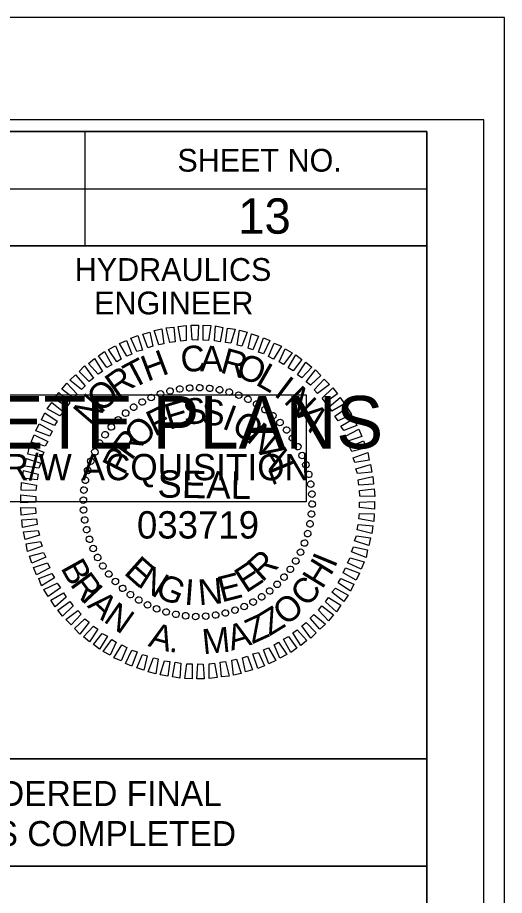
# Model space of a CAD drawing. Extents: x 1779926 to 1781610, y 620464 to 621564.
# Drawn here: x 1781503.2 to 1781610, y 621371.7 to 621564.2 of the extents above; entities that cross this region are included whole.
import ezdxf

# ---------------------------------------------------------------- set-up
doc = ezdxf.new("R2010")
doc.units = 0
for name, color, linetype in [('Old_Level_58', 7, 'Continuous'), ('Sheet Cutting Line CELL', 7, 'Continuous'), ('Sheet Data Field CELL', 7, 'Continuous'), ('Sheet Plot Border Inside CELL', 7, 'Continuous'), ('Sheet Plot Border Outside CELL', 7, 'Continuous'), ('Sheet Professional Seal CELL', 7, 'Continuous'), ('Sheet Profile CELL', 7, 'Continuous'), ('Sheet Profile Grid Major CELL', 7, 'Continuous'), ('Sheet Profile Grid Minor CELL', 7, 'Continuous'), ('Sheet Sticker Exception Certification CELL', 7, 'Continuous'), ('Sheet Sticker Incomplete CELL', 7, 'Continuous')]:
    doc.layers.add(name, color=color, linetype=linetype)

msp = doc.modelspace()

# ---------------------------------------------------------------- linework, layer by layer
at = {"layer": 'Old_Level_58'}
msp.add_lwpolyline([(1781392.9, 621378.13), (1781592.95, 621378.13), (1781592.95, 621314.19), (1781392.9, 621314.19)], close=True, dxfattribs=at)
at = {"layer": 'Sheet Cutting Line CELL'}
msp.add_line((1781609.96, 621564.19), (1779925.96, 621564.19), dxfattribs=at)
at = {"layer": 'Sheet Plot Border Inside CELL'}
msp.add_lwpolyline([(1779938.96, 620486.64), (1781605.46, 620486.64), (1781605.46, 621541.74), (1779938.96, 621541.74)], close=True, dxfattribs=at)
at = {"layer": 'Sheet Plot Border Outside CELL'}
msp.add_lwpolyline([(1779925.96, 620464.19), (1781609.96, 620464.19), (1781609.96, 621564.19), (1779925.96, 621564.19)], close=True, dxfattribs=at)
at = {"layer": 'Sheet Professional Seal CELL'}
for p, q in [((1781538.82, 621482.71), (1781538.82, 621482.71)), ((1781540.97, 621483.01), (1781540.97, 621483.01)), ((1781543.17, 621483.06), (1781543.17, 621483.06)), ((1781545.37, 621482.91), (1781545.37, 621482.91)), ((1781547.52, 621482.56), (1781547.52, 621482.56)), ((1781532.52, 621480.91), (1781532.52, 621480.91)), ((1781534.52, 621481.71), (1781534.52, 621481.71)), ((1781536.62, 621482.31), (1781536.62, 621482.31)), ((1781549.62, 621482.11), (1781549.62, 621482.11)), ((1781551.72, 621481.41), (1781551.72, 621481.41)), ((1781553.72, 621480.51), (1781553.72, 621480.51)), ((1781528.67, 621478.76), (1781528.67, 621478.76)), ((1781530.57, 621479.91), (1781530.57, 621479.91)), ((1781555.67, 621479.51), (1781555.67, 621479.51)), ((1781526.92, 621477.51), (1781526.92, 621477.51)), ((1781557.47, 621478.26), (1781557.47, 621478.26)), ((1781559.22, 621476.91), (1781559.22, 621476.91)), ((1781525.27, 621476.01), (1781525.27, 621476.01)), ((1781560.77, 621475.41), (1781560.77, 621475.41)), ((1781523.77, 621474.46), (1781523.77, 621474.46)), ((1781562.27, 621473.76), (1781562.27, 621473.76)), ((1781521.17, 621470.91), (1781521.17, 621470.91)), ((1781522.42, 621472.71), (1781522.42, 621472.71)), ((1781563.52, 621472.01), (1781563.52, 621472.01)), ((1781520.17, 621468.96), (1781520.17, 621468.96)), ((1781564.67, 621470.11), (1781564.67, 621470.11)), ((1781565.67, 621468.16), (1781565.67, 621468.16)), ((1781519.27, 621466.96), (1781519.27, 621466.96)), ((1781566.47, 621466.16), (1781566.47, 621466.16)), ((1781518.57, 621464.86), (1781518.57, 621464.86)), ((1781567.07, 621464.06), (1781567.07, 621464.06)), ((1781518.12, 621462.76), (1781518.12, 621462.76)), ((1781567.47, 621461.86), (1781567.47, 621461.86)), ((1781517.77, 621460.61), (1781517.77, 621460.61)), ((1781567.77, 621459.71), (1781567.77, 621459.71)), ((1781517.62, 621458.41), (1781517.62, 621458.41)), ((1781542.72, 621457.96), (1781542.72, 621457.96)), ((1781567.82, 621457.51), (1781567.82, 621457.51)), ((1781517.67, 621456.21), (1781517.67, 621456.21)), ((1781517.97, 621454.06), (1781517.97, 621454.06)), ((1781567.67, 621455.31), (1781567.67, 621455.31)), ((1781518.37, 621451.86), (1781518.37, 621451.86)), ((1781567.32, 621453.16), (1781567.32, 621453.16)), ((1781518.97, 621449.76), (1781518.97, 621449.76)), ((1781566.87, 621451.06), (1781566.87, 621451.06)), ((1781519.77, 621447.76), (1781519.77, 621447.76)), ((1781566.17, 621448.96), (1781566.17, 621448.96)), ((1781565.27, 621446.96), (1781565.27, 621446.96)), ((1781520.77, 621445.81), (1781520.77, 621445.81)), ((1781521.92, 621443.91), (1781521.92, 621443.91)), ((1781564.27, 621445.01), (1781564.27, 621445.01)), ((1781523.17, 621442.16), (1781523.17, 621442.16)), ((1781563.02, 621443.21), (1781563.02, 621443.21)), ((1781524.67, 621440.51), (1781524.67, 621440.51)), ((1781561.67, 621441.46), (1781561.67, 621441.46)), ((1781526.22, 621439.01), (1781526.22, 621439.01)), ((1781558.52, 621438.41), (1781558.52, 621438.41)), ((1781560.17, 621439.91), (1781560.17, 621439.91)), ((1781527.97, 621437.66), (1781527.97, 621437.66)), ((1781529.77, 621436.41), (1781529.77, 621436.41)), ((1781556.77, 621437.16), (1781556.77, 621437.16)), ((1781531.72, 621435.41), (1781531.72, 621435.41)), ((1781533.72, 621434.51), (1781533.72, 621434.51)), ((1781552.92, 621435.01), (1781552.92, 621435.01)), ((1781554.87, 621436.01), (1781554.87, 621436.01)), ((1781535.82, 621433.81), (1781535.82, 621433.81)), ((1781537.92, 621433.36), (1781537.92, 621433.36)), ((1781540.07, 621433.01), (1781540.07, 621433.01)), ((1781542.27, 621432.86), (1781542.27, 621432.86)), ((1781544.47, 621432.91), (1781544.47, 621432.91)), ((1781546.62, 621433.21), (1781546.62, 621433.21)), ((1781548.82, 621433.61), (1781548.82, 621433.61)), ((1781550.92, 621434.21), (1781550.92, 621434.21))]:
    msp.add_line(p, q, dxfattribs=at)
for points in [[(1781534.22, 621492.41), (1781533.17, 621495.56), (1781534.87, 621495.91), (1781535.27, 621492.66)], [(1781536.62, 621492.96), (1781535.82, 621496.16), (1781537.47, 621496.31), (1781537.82, 621493.11)], [(1781539.02, 621493.26), (1781538.47, 621496.46), (1781540.17, 621496.66), (1781540.22, 621493.41)], [(1781541.52, 621493.51), (1781541.27, 621496.76), (1781542.92, 621496.71), (1781542.72, 621493.46)], [(1781543.92, 621493.46), (1781543.92, 621496.71), (1781545.57, 621496.66), (1781545.12, 621493.41)], [(1781546.42, 621493.31), (1781546.62, 621496.56), (1781548.27, 621496.26), (1781547.62, 621493.11)], [(1781548.82, 621492.91), (1781549.27, 621496.11), (1781550.92, 621495.86), (1781550.02, 621492.76)], [(1781529.37, 621490.96), (1781528.07, 621493.86), (1781529.57, 621494.46), (1781530.62, 621491.26)], [(1781531.82, 621491.76), (1781530.67, 621494.76), (1781532.22, 621495.21), (1781532.87, 621492.11)], [(1781551.37, 621492.36), (1781551.87, 621495.61), (1781553.57, 621495.21), (1781552.42, 621492.11)], [(1781553.77, 621491.71), (1781554.52, 621494.81), (1781556.07, 621494.31), (1781554.82, 621491.36)], [(1781556.02, 621490.81), (1781557.17, 621493.96), (1781558.57, 621493.36), (1781557.17, 621490.46)], [(1781525.02, 621488.71), (1781523.17, 621491.41), (1781524.72, 621492.21), (1781525.97, 621489.31)], [(1781527.17, 621489.91), (1781525.57, 621492.71), (1781527.12, 621493.41), (1781528.27, 621490.36)], [(1781558.27, 621489.86), (1781559.52, 621492.81), (1781561.07, 621492.11), (1781559.37, 621489.31)], [(1781522.82, 621487.46), (1781520.97, 621490.01), (1781522.27, 621490.96), (1781523.92, 621488.06)], [(1781560.57, 621488.71), (1781561.92, 621491.56), (1781563.42, 621490.71), (1781561.52, 621488.11)], [(1781562.52, 621487.36), (1781564.27, 621490.26), (1781565.57, 621489.21), (1781563.62, 621486.76)], [(1781520.92, 621485.96), (1781518.77, 621488.36), (1781520.12, 621489.41), (1781521.87, 621486.61)], [(1781564.57, 621485.86), (1781566.42, 621488.61), (1781567.72, 621487.51), (1781565.52, 621485.16)], [(1781518.92, 621484.41), (1781516.72, 621486.61), (1781517.92, 621487.81), (1781519.87, 621485.11)], [(1781566.47, 621484.31), (1781568.52, 621486.91), (1781569.72, 621485.71), (1781567.42, 621483.56)], [(1781517.27, 621482.66), (1781514.72, 621484.71), (1781515.97, 621485.86), (1781518.07, 621483.46)], [(1781568.27, 621482.56), (1781570.42, 621484.91), (1781571.62, 621483.71), (1781569.02, 621481.76)], [(1781515.52, 621480.76), (1781512.92, 621482.71), (1781514.02, 621484.01), (1781516.22, 621481.66)], [(1781570.02, 621480.76), (1781572.32, 621483.01), (1781573.37, 621481.66), (1781570.72, 621479.76)], [(1781514.02, 621478.86), (1781511.32, 621480.56), (1781512.27, 621482.01), (1781514.67, 621479.81)], [(1781571.52, 621478.81), (1781573.97, 621480.91), (1781574.92, 621479.46), (1781572.12, 621477.86)], [(1781512.52, 621476.86), (1781509.72, 621478.36), (1781510.72, 621479.76), (1781513.32, 621477.76)], [(1781572.82, 621476.76), (1781575.47, 621478.66), (1781576.42, 621477.16), (1781573.52, 621475.76)], [(1781511.32, 621474.71), (1781508.47, 621475.96), (1781509.22, 621477.51), (1781511.92, 621475.66)], [(1781510.32, 621472.41), (1781507.22, 621473.56), (1781507.97, 621475.11), (1781510.82, 621473.51)], [(1781574.12, 621474.56), (1781576.92, 621476.31), (1781577.57, 621474.76), (1781574.72, 621473.61)], [(1781575.12, 621472.41), (1781578.07, 621473.91), (1781578.72, 621472.31), (1781575.62, 621471.31)], [(1781509.32, 621470.21), (1781506.22, 621471.11), (1781506.87, 621472.66), (1781509.87, 621471.26)], [(1781576.02, 621470.06), (1781579.07, 621471.36), (1781579.62, 621469.81), (1781576.52, 621469.01)], [(1781508.57, 621467.81), (1781505.47, 621468.46), (1781505.82, 621470.11), (1781508.97, 621468.86)], [(1781507.92, 621465.41), (1781504.82, 621465.81), (1781505.17, 621467.51), (1781508.32, 621466.46)], [(1781576.82, 621467.66), (1781580.02, 621468.81), (1781580.32, 621467.16), (1781577.17, 621466.61)], [(1781577.42, 621465.26), (1781580.57, 621466.21), (1781580.87, 621464.51), (1781577.72, 621464.21)], [(1781507.52, 621462.86), (1781504.32, 621463.16), (1781504.52, 621464.86), (1781507.77, 621464.06)], [(1781577.87, 621462.86), (1781581.12, 621463.56), (1781581.27, 621461.86), (1781578.07, 621461.66)], [(1781507.27, 621460.46), (1781504.02, 621460.56), (1781504.12, 621462.21), (1781507.37, 621461.66)], [(1781507.22, 621457.96), (1781503.97, 621457.81), (1781503.97, 621459.51), (1781507.22, 621459.16)], [(1781578.17, 621460.46), (1781581.42, 621460.86), (1781581.52, 621459.16), (1781578.27, 621459.26)], [(1781578.22, 621457.96), (1781581.47, 621458.11), (1781581.47, 621456.41), (1781578.22, 621456.76)], [(1781507.27, 621455.46), (1781504.02, 621455.06), (1781503.92, 621456.76), (1781507.17, 621456.66)], [(1781578.17, 621455.46), (1781581.42, 621455.36), (1781581.32, 621453.71), (1781578.07, 621454.26)], [(1781507.57, 621453.06), (1781504.32, 621452.36), (1781504.17, 621454.06), (1781507.37, 621454.26)], [(1781508.02, 621450.66), (1781504.87, 621449.71), (1781504.57, 621451.41), (1781507.72, 621451.71)], [(1781577.92, 621453.06), (1781581.12, 621452.76), (1781580.92, 621451.06), (1781577.67, 621451.86)], [(1781577.52, 621450.51), (1781580.62, 621450.11), (1781580.27, 621448.41), (1781577.12, 621449.46)], [(1781508.62, 621448.26), (1781505.42, 621447.11), (1781505.12, 621448.76), (1781508.27, 621449.31)], [(1781576.87, 621448.11), (1781579.97, 621447.46), (1781579.62, 621445.81), (1781576.47, 621447.06)], [(1781509.42, 621445.86), (1781506.37, 621444.56), (1781505.82, 621446.11), (1781508.92, 621446.91)], [(1781510.32, 621443.51), (1781507.37, 621442.01), (1781506.72, 621443.61), (1781509.82, 621444.61)], [(1781576.12, 621445.71), (1781579.22, 621444.81), (1781578.57, 621443.26), (1781575.57, 621444.66)], [(1781511.32, 621441.36), (1781508.52, 621439.61), (1781507.87, 621441.16), (1781510.72, 621442.31)], [(1781575.12, 621443.51), (1781578.22, 621442.36), (1781577.47, 621440.81), (1781574.62, 621442.41)], [(1781512.62, 621439.16), (1781509.97, 621437.26), (1781509.02, 621438.76), (1781511.92, 621440.16)], [(1781574.12, 621441.21), (1781576.97, 621439.96), (1781576.22, 621438.41), (1781573.52, 621440.26)], [(1781572.92, 621439.06), (1781575.72, 621437.56), (1781574.72, 621436.16), (1781572.12, 621438.16)], [(1781513.92, 621437.11), (1781511.47, 621435.01), (1781510.52, 621436.46), (1781513.32, 621438.06)], [(1781571.42, 621437.06), (1781574.12, 621435.36), (1781573.17, 621433.91), (1781570.77, 621436.11)], [(1781515.42, 621435.16), (1781513.12, 621432.91), (1781512.07, 621434.26), (1781514.72, 621436.16)], [(1781569.92, 621435.16), (1781572.52, 621433.21), (1781571.42, 621431.91), (1781569.22, 621434.26)], [(1781517.17, 621433.36), (1781515.02, 621431.01), (1781513.82, 621432.21), (1781516.42, 621434.16)], [(1781518.97, 621431.61), (1781516.92, 621429.01), (1781515.72, 621430.21), (1781518.02, 621432.36)], [(1781568.17, 621433.26), (1781570.72, 621431.21), (1781569.47, 621430.06), (1781567.37, 621432.46)], [(1781520.87, 621430.06), (1781519.02, 621427.31), (1781517.72, 621428.41), (1781519.92, 621430.76)], [(1781566.52, 621431.51), (1781568.72, 621429.31), (1781567.52, 621428.11), (1781565.57, 621430.81)], [(1781522.92, 621428.56), (1781521.17, 621425.66), (1781519.87, 621426.71), (1781521.82, 621429.16)], [(1781564.52, 621429.96), (1781566.67, 621427.56), (1781565.32, 621426.51), (1781563.57, 621429.31)], [(1781524.87, 621427.21), (1781523.52, 621424.36), (1781522.02, 621425.21), (1781523.92, 621427.81)], [(1781527.17, 621426.06), (1781525.92, 621423.11), (1781524.37, 621423.81), (1781526.07, 621426.61)], [(1781560.42, 621427.21), (1781562.27, 621424.51), (1781560.72, 621423.71), (1781559.47, 621426.61)], [(1781562.62, 621428.46), (1781564.47, 621425.91), (1781563.17, 621424.96), (1781561.52, 621427.86)], [(1781529.42, 621425.11), (1781528.27, 621421.96), (1781526.87, 621422.56), (1781528.27, 621425.46)], [(1781556.07, 621424.96), (1781557.37, 621422.06), (1781555.87, 621421.46), (1781554.82, 621424.66)], [(1781558.27, 621426.01), (1781559.87, 621423.21), (1781558.32, 621422.51), (1781557.17, 621425.56)], [(1781531.67, 621424.21), (1781530.92, 621421.11), (1781529.37, 621421.61), (1781530.62, 621424.56)], [(1781534.07, 621423.56), (1781533.57, 621420.31), (1781531.87, 621420.71), (1781533.02, 621423.81)], [(1781536.62, 621423.01), (1781536.17, 621419.81), (1781534.52, 621420.06), (1781535.42, 621423.16)], [(1781539.02, 621422.61), (1781538.82, 621419.36), (1781537.17, 621419.66), (1781537.82, 621422.81)], [(1781548.82, 621422.96), (1781549.62, 621419.76), (1781547.97, 621419.61), (1781547.62, 621422.81)], [(1781551.22, 621423.51), (1781552.27, 621420.36), (1781550.57, 621420.01), (1781550.17, 621423.26)], [(1781553.62, 621424.16), (1781554.77, 621421.16), (1781553.22, 621420.71), (1781552.57, 621423.81)], [(1781541.52, 621422.46), (1781541.52, 621419.21), (1781539.87, 621419.26), (1781540.32, 621422.51)], [(1781543.92, 621422.41), (1781544.17, 621419.16), (1781542.52, 621419.21), (1781542.72, 621422.46)], [(1781546.42, 621422.66), (1781546.97, 621419.46), (1781545.27, 621419.26), (1781545.22, 621422.51)]]:
    msp.add_lwpolyline(points, close=True, dxfattribs=at)
for centre, major_axis in [((1781534.56, 621481.67), (-0.234, 0.681)), ((1781536.65, 621482.29), (-0.174, 0.699)), ((1781538.8, 621482.73), (-0.113, 0.711)), ((1781540.97, 621482.97), (-0.05, 0.718)), ((1781543.16, 621483.03), (0.013, 0.72)), ((1781545.34, 621482.9), (0.075, 0.716)), ((1781547.51, 621482.57), (0.137, 0.707)), ((1781549.64, 621482.06), (0.198, 0.692)), ((1781530.56, 621479.89), (-0.349, 0.63)), ((1781532.52, 621480.87), (-0.293, 0.658)), ((1781551.71, 621481.37), (0.258, 0.672)), ((1781553.72, 621480.5), (0.316, 0.647)), ((1781528.7, 621478.75), (-0.403, 0.597)), ((1781555.64, 621479.45), (0.371, 0.617)), ((1781557.46, 621478.25), (0.423, 0.582)), ((1781525.3, 621476), (-0.5, 0.518)), ((1781526.94, 621477.45), (-0.453, 0.56)), ((1781559.18, 621476.88), (0.472, 0.543)), ((1781523.79, 621474.41), (-0.543, 0.472)), ((1781560.76, 621475.38), (0.518, 0.5)), ((1781522.43, 621472.7), (-0.582, 0.423)), ((1781562.21, 621473.74), (0.56, 0.453)), ((1781563.51, 621471.98), (0.597, 0.403)), ((1781521.22, 621470.87), (-0.617, 0.371)), ((1781564.66, 621470.11), (0.63, 0.349)), ((1781520.18, 621468.95), (-0.647, 0.316)), ((1781565.63, 621468.16), (0.658, 0.293)), ((1781519.31, 621466.94), (-0.672, 0.258)), ((1781518.61, 621464.87), (-0.692, 0.198)), ((1781566.44, 621466.12), (0.681, 0.234)), ((1781518.1, 621462.74), (-0.707, 0.137)), ((1781567.06, 621464.02), (0.699, 0.174)), ((1781517.78, 621460.58), (-0.716, 0.075)), ((1781567.49, 621461.88), (0.711, 0.113)), ((1781567.74, 621459.7), (0.718, 0.05)), ((1781517.65, 621458.39), (-0.72, 0.013)), ((1781567.8, 621457.52), (0.72, -0.013)), ((1781517.7, 621456.21), (-0.718, -0.05)), ((1781567.66, 621455.33), (0.716, -0.075)), ((1781517.95, 621454.03), (-0.711, -0.113)), ((1781567.34, 621453.17), (0.707, -0.137)), ((1781518.39, 621451.89), (-0.699, -0.174)), ((1781566.83, 621451.04), (0.692, -0.198)), ((1781519.01, 621449.79), (-0.681, -0.234)), ((1781566.14, 621448.97), (0.672, -0.258)), ((1781519.81, 621447.75), (-0.658, -0.293)), ((1781565.26, 621446.96), (0.647, -0.316)), ((1781520.79, 621445.8), (-0.63, -0.349)), ((1781564.22, 621445.04), (0.617, -0.371)), ((1781521.93, 621443.93), (-0.597, -0.403)), ((1781563.01, 621443.21), (0.582, -0.423)), ((1781523.23, 621442.17), (-0.56, -0.453)), ((1781561.65, 621441.5), (0.543, -0.472)), ((1781524.68, 621440.53), (-0.518, -0.5)), ((1781560.14, 621439.91), (0.5, -0.518)), ((1781526.27, 621439.03), (-0.472, -0.543)), ((1781527.98, 621437.67), (-0.423, -0.582)), ((1781558.51, 621438.46), (0.453, -0.56)), ((1781529.81, 621436.46), (-0.371, -0.617)), ((1781531.73, 621435.41), (-0.316, -0.647)), ((1781554.88, 621436.02), (0.349, -0.63)), ((1781556.75, 621437.16), (0.403, -0.597)), ((1781533.73, 621434.54), (-0.258, -0.672)), ((1781535.81, 621433.85), (-0.198, -0.692)), ((1781548.79, 621433.62), (0.174, -0.699)), ((1781550.89, 621434.24), (0.234, -0.681)), ((1781552.92, 621435.04), (0.293, -0.658)), ((1781537.94, 621433.34), (-0.137, -0.707)), ((1781540.1, 621433.01), (-0.075, -0.716)), ((1781542.28, 621432.88), (-0.013, -0.72)), ((1781544.47, 621432.94), (0.05, -0.718)), ((1781546.65, 621433.18), (0.113, -0.711))]:
    msp.add_ellipse(centre, major_axis=major_axis, ratio=0.999708, dxfattribs=at)
at = {"layer": 'Sheet Profile CELL'}
for p, q in [((1781517.96, 621539.14), (1781517.96, 621514.14)), ((1781392.91, 621526.64), (1781592.96, 621526.64))]:
    msp.add_line(p, q, dxfattribs=at)
for points in [[(1781592.96, 621539.19), (1780092.96, 621539.19), (1780092.96, 620489.19), (1781592.96, 620489.19)], [(1781392.91, 621539.19), (1781592.96, 621539.19), (1781592.96, 621514.14), (1781392.91, 621514.14)], [(1781492.96, 621514.14), (1781592.96, 621514.14), (1781592.96, 621401.64), (1781492.96, 621401.64)]]:
    msp.add_lwpolyline(points, close=True, dxfattribs=at)
at = {"layer": 'Sheet Profile Grid Major CELL'}
msp.add_lwpolyline([(1781542.96, 621314.19), (1781542.96, 621039.19), (1781592.96, 621039.19), (1781592.96, 621389.19)], dxfattribs=at)
at = {"layer": 'Sheet Sticker Exception Certification CELL'}
for p, q in [((1781392.91, 621401.64), (1781592.95, 621401.64)), ((1781392.91, 621401.64), (1781592.95, 621401.64)), ((1781592.95, 621401.63), (1781592.95, 621378.13)), ((1781592.95, 621401.63), (1781592.95, 621378.13)), ((1781592.95, 621378.14), (1781392.91, 621378.14)), ((1781592.95, 621378.14), (1781392.91, 621378.14))]:
    msp.add_line(p, q, dxfattribs=at)
at = {"layer": 'Sheet Sticker Incomplete CELL'}
msp.add_lwpolyline([(1781419.48, 621457.99), (1781419.48, 621481.49), (1781566.48, 621481.49), (1781566.48, 621457.99)], close=True, dxfattribs=at)

# ---------------------------------------------------------------- texts
at = {"layer": 'Sheet Data Field CELL'}
msp.add_text('13', height=7.75, dxfattribs=at).set_placement((1781551.6, 621516.8))
at = {"layer": 'Sheet Professional Seal CELL'}
for s, height, rotation, p in [('C', 5.64, 6.2199, (1781539.27, 621486.31)), ('A', 5.64, 359.0203, (1781543.22, 621486.61)), ('H', 5.64, 20.6195, (1781531.67, 621484.31)), ('R', 5.64, 344.6211, (1781547.42, 621486.41)), ('O', 5.64, 337.4212, (1781550.77, 621485.66)), ('T', 5.64, 27.8198, (1781528.42, 621482.66)), ('L', 5.64, 330.2209, (1781555.17, 621483.81)), ('R', 5.64, 35.0205, (1781525.02, 621480.46)), ('O', 5.64, 42.2217, (1781521.57, 621477.36)), ('I', 5.64, 323.0201, (1781559.22, 621481.41)), ('N', 5.64, 315.8189, (1781561.37, 621479.86)), ('N', 5.64, 49.4235, (1781519.27, 621474.46)), ('S', 5.64, 7.2556, (1781539.92, 621474.81)), ('S', 5.64, 357.9004, (1781543.52, 621474.86)), ('F', 5.64, 25.967, (1781533.27, 621472.26)), ('E', 5.64, 16.6111, (1781536.47, 621473.76)), ('I', 5.64, 339.1896, (1781547.82, 621474.16)), ('A', 5.64, 308.6172, (1781564.32, 621476.91)), ('O', 5.64, 329.8335, (1781549.82, 621473.46)), ('O', 5.64, 44.6812, (1781529.97, 621469.31)), ('N', 5.64, 320.4766, (1781553.17, 621471.46)), ('R', 5.64, 54.0397, (1781528.22, 621466.86)), ('P', 5.64, 63.3989, (1781526.62, 621463.66)), ('A', 5.64, 301.7603, (1781556.02, 621468.86)), ('L', 5.64, 292.4008, (1781557.97, 621465.41)), ('SEAL', 5.998, 359, (1781533.87, 621458.96)), ('E', 5.64, 318.2769, (1781526.32, 621442.31)), ('R', 5.64, 42.4814, (1781556.82, 621440.21)), ('N', 5.64, 327.634, (1781529.32, 621439.61)), ('E', 5.64, 33.1241, (1781553.27, 621437.86)), ('E', 5.64, 14.4118, (1781547.97, 621435.91)), ('G', 5.64, 336.9902, (1781533.12, 621437.36)), ('I', 5.64, 355.7012, (1781539.67, 621435.46)), ('N', 5.64, 5.0564, (1781543.02, 621435.31))]:
    msp.add_text(s, height=height, rotation=rotation, dxfattribs=at).set_placement(p)
at = {"layer": 'Sheet Profile CELL'}
for s, p in [('SHEET NO.', (1781538.27, 621530.4)), ('HYDRAULICS', (1781515.77, 621506.45)), ('ENGINEER', (1781520.02, 621499.1))]:
    msp.add_text(s, height=5, dxfattribs=at).set_placement(p)
at = {"layer": 'Sheet Profile Grid Minor CELL'}
msp.add_text('033719', height=5.998, dxfattribs=at).set_placement((1781529.41, 621449.95))
for s, rotation, p in [('I', 67.5926, (1781572.78, 621443.32)), ('B', 299.1529, (1781512.57, 621443.51)), ('H', 58.3478, (1781570.03, 621438.68)), ('R', 306.2797, (1781514.6, 621439.89)), ('C', 49.4751, (1781566.73, 621434.7)), ('I', 313.2061, (1781516.98, 621436.63)), ('A', 316.7266, (1781518.34, 621435.09)), ('O', 38.7706, (1781562, 621430.64)), ('N', 324.9124, (1781521.85, 621431.85)), ('Z', 31.6438, (1781558.46, 621428.46)), ('Z', 24.517, (1781554.68, 621426.74)), ('A', 344.2893, (1781531.69, 621426.4)), ('M', 5.6554, (1781543.95, 621424.55)), ('A', 16.3312, (1781550.11, 621425.35)), ('.', 352.4751, (1781536.3, 621425.15))]:
    msp.add_text(s, height=5.5, rotation=rotation, dxfattribs=at).set_placement(p)
at = {"layer": 'Sheet Sticker Exception Certification CELL'}
for s, p in [('DOCUMENT NOT CONSIDERED FINAL', (1781413.98, 621391.3)), ('DOCUMENT NOT CONSIDERED FINAL', (1781413.98, 621391.3)), ('UNLESS ALL SIGNATURES COMPLETED', (1781408.91, 621382.5)), ('UNLESS ALL SIGNATURES COMPLETED', (1781408.91, 621382.5))]:
    msp.add_text(s, height=5.5, dxfattribs=at).set_placement(p)
at = {"layer": 'Sheet Sticker Incomplete CELL'}
for s, height, p in [('INCOMPLETE PLANS', 11.52, (1781428.43, 621469.69)), ('DO NOT USE FOR R/W ACQUISITION', 5.76, (1781431.68, 621462.74))]:
    msp.add_text(s, height=height, dxfattribs=at).set_placement(p)

doc.saveas('drawing.dxf')
